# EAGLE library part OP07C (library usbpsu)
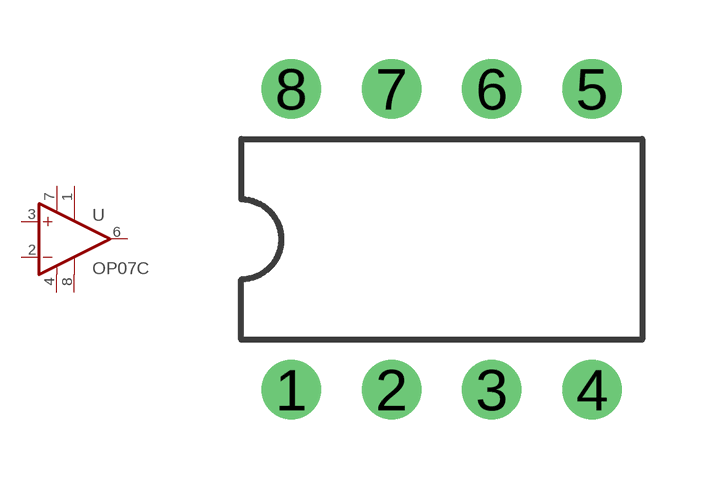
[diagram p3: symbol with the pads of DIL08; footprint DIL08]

Designator prefix -

## OP07CP  [DIL08]
1  TRIM1  pas
2  -IN  in
3  +IN  in
4  V-  pwr
6  OUT  out
7  V+  pwr
8  TRIM2  pas

## Footprint DIL08 (pad centres in mm)
Dual In Line
drill 1 round: 1 -3.81,-3.81; 2 -1.27,-3.81; 3 1.27,-3.81; 4 3.81,-3.81; 5 3.81,3.81; 6 1.27,3.81; 7 -1.27,3.81; 8 -3.81,3.81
